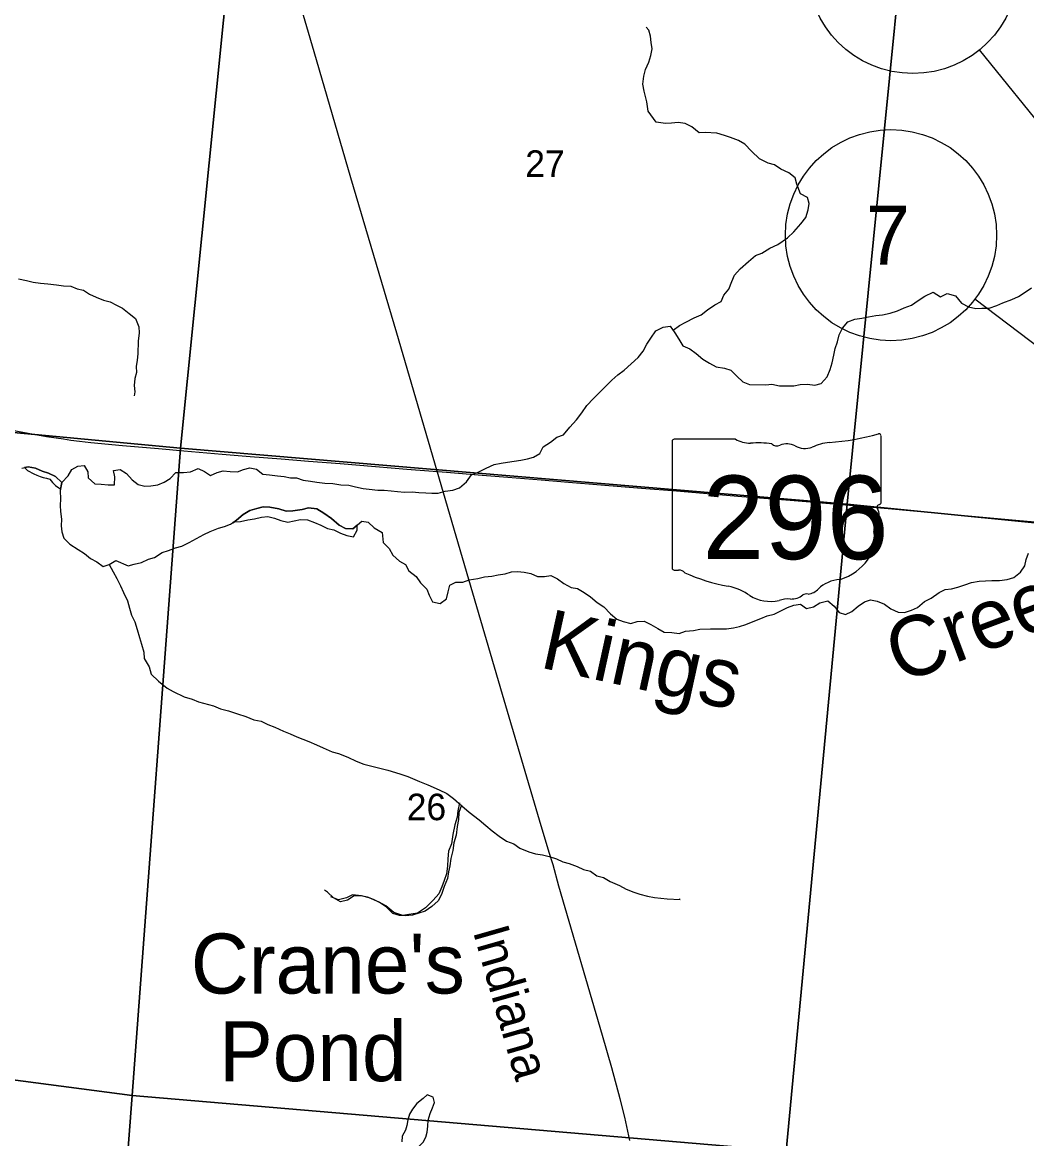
# Model space of a CAD drawing. Extents: x 0 to 1101, y 0 to 440.
# Drawn here: x 194.8 to 242.4, y 64.6 to 117.4 of the extents above; entities that cross this region are included whole.
import ezdxf

# ---------------------------------------------------------------- set-up
doc = ezdxf.new("R2010")
doc.units = 0
for name, color, linetype in [('GM_X_Minor_Lake', 7, 'Continuous'), ('GM_X_Minor_River', 7, 'Continuous'), ('GM_X_Minor_River_Text', 7, 'Continuous'), ('GM_X_Rail_Line', 7, 'Continuous'), ('GM_X_Rail_Line_Text', 7, 'Continuous'), ('GM_X_Section', 7, 'Continuous'), ('GM_X_Section_Text', 7, 'Continuous'), ('GM_X_State_Location', 7, 'Continuous'), ('GM_X_State_Route', 7, 'Continuous'), ('GM_X_State_Shield', 7, 'Continuous'), ('SH_Masking', 7, 'Continuous'), ('SH_Text', 7, 'Continuous')]:
    doc.layers.add(name, color=color, linetype=linetype)

msp = doc.modelspace()

# ---------------------------------------------------------------- linework, layer by layer
at = {"layer": 'GM_X_Minor_Lake'}
for points in [[(196.719, 95.648), (196.408, 95.92), (196.083, 96.089), (195.778, 96.178), (195.464, 96.313), (195.124, 96.38), (194.949, 96.347)], [(194.949, 96.347), (195.093, 96.204), (195.388, 96.047), (195.533, 95.99), (195.684, 95.93), (195.832, 95.882), (195.989, 95.84), (196.14, 95.792), (196.275, 95.644), (196.42, 95.502), (196.565, 95.382), (196.653, 95.312)], [(196.653, 95.312), (196.719, 95.648)], [(210.69, 93.617), (210.487, 93.446), (210.146, 93.468), (209.844, 93.625), (209.488, 93.933), (209.12, 94.184), (208.785, 94.399), (208.398, 94.434), (208.1, 94.362), (207.643, 94.296), (207.335, 94.282), (206.986, 94.395), (206.555, 94.477), (206.248, 94.486), (205.939, 94.415), (205.617, 94.311), (205.293, 94.126), (204.989, 93.85), (204.809, 93.735)], [(204.809, 93.735), (204.884, 93.773), (205.169, 93.798), (205.513, 93.868), (205.834, 93.927), (206.166, 93.997), (206.474, 94.034), (206.779, 93.956), (207.083, 93.833), (207.411, 93.755), (207.709, 93.826), (208.018, 93.885), (208.348, 93.875), (208.675, 93.751), (208.978, 93.617), (209.292, 93.459), (209.598, 93.393), (209.9, 93.235), (210.205, 93.135), (210.522, 93.068), (210.702, 93.383), (210.69, 93.617)], [(212.694, 60.754), (212.77, 60.75), (212.842, 60.999), (212.851, 61.545), (212.798, 61.807), (212.769, 62.126), (212.784, 62.365), (212.8, 62.637), (212.85, 62.932), (212.933, 63.17), (213.05, 63.453), (213.224, 63.689), (213.444, 63.947), (213.618, 64.184), (213.825, 64.397), (213.953, 64.622), (214.014, 64.86), (214.041, 65.156), (214.057, 65.428), (214.152, 65.745), (214.27, 66.017), (214.365, 66.277), (214.289, 66.528), (214.019, 66.635)], [(214.019, 66.635), (213.823, 66.467), (213.524, 66.221), (213.316, 65.963), (213.176, 65.715), (213.093, 65.443), (213.055, 65.182), (212.983, 64.955), (212.831, 64.673), (212.804, 64.401)]]:
    msp.add_lwpolyline(points, dxfattribs=at)
at = {"layer": 'GM_X_Minor_River'}
for points in [[(225.652, 102.856), (225.956, 103.071), (226.256, 103.234), (226.649, 103.439), (226.984, 103.577), (227.287, 103.82), (227.635, 104.049), (227.924, 104.212), (228.058, 104.516), (228.295, 104.806), (228.441, 105.156), (228.564, 105.46), (228.835, 105.76), (229.221, 106.103), (229.559, 106.39), (229.858, 106.506), (230.241, 106.735), (230.61, 106.918), (231.075, 107.224), (231.368, 107.512), (231.709, 107.89), (231.934, 108.192), (232.047, 108.554), (232.09, 108.849), (232.019, 109.148), (231.694, 109.318), (231.514, 109.78), (231.432, 110.079), (231.131, 110.316), (230.76, 110.487), (230.459, 110.69), (230.154, 110.768), (229.739, 110.974), (229.362, 111.328), (229.053, 111.668), (228.751, 111.848), (228.379, 111.985), (228.086, 112.085), (227.725, 112.187), (227.18, 112.226), (226.883, 112.2), (226.538, 112.484), (226.224, 112.642), (225.895, 112.697), (225.587, 112.661), (225.302, 112.647), (224.849, 112.717), (224.477, 113.23), (224.41, 113.677), (224.288, 114.172), (224.218, 114.516), (224.263, 114.892), (224.352, 115.208), (224.499, 115.558), (224.599, 115.863), (224.665, 116.18), (224.617, 116.479), (224.592, 116.776), (224.51, 117.075), (224.377, 117.216)], [(194.667, 105.289), (195.04, 105.209), (195.357, 105.131), (195.709, 105.087), (196.049, 105.054), (196.457, 104.996), (196.787, 104.963), (197.139, 104.942), (197.442, 104.807), (197.737, 104.753), (198.027, 104.561), (198.342, 104.427), (198.679, 104.28), (198.996, 104.202), (199.298, 104.033), (199.59, 103.899), (199.902, 103.65), (200.202, 103.413), (200.361, 103.02), (200.376, 102.734), (200.33, 102.335), (200.313, 101.742), (200.281, 101.435), (200.238, 101.139), (200.253, 100.853), (200.176, 100.559), (200.132, 100.24), (200.169, 99.942), (200.14, 99.738)], [(213.611, 95.17), (213.952, 95.148), (214.237, 95.14), (214.533, 95.142), (214.865, 95.224), (215.231, 95.27), (215.542, 95.386), (215.88, 95.673), (216.106, 95.998), (216.429, 96.137), (216.799, 96.32), (217.179, 96.491), (217.511, 96.55), (217.809, 96.598), (218.129, 96.646), (218.449, 96.705), (218.758, 96.764), (219.045, 96.836), (219.346, 97.021), (219.503, 97.324), (219.852, 97.554), (220.154, 97.785), (220.465, 97.901), (220.772, 98.269), (221.078, 98.614), (221.338, 98.937), (221.564, 99.285), (221.881, 99.618), (222.174, 99.906), (222.456, 100.195), (222.749, 100.483), (223.041, 100.737), (223.344, 100.956), (223.999, 101.554), (224.235, 101.866), (224.404, 102.192), (224.595, 102.484), (224.844, 102.819), (225.191, 103.003), (225.522, 103.05), (225.74, 102.724), (225.926, 102.433), (226.121, 102.107), (226.447, 101.972), (226.748, 101.757), (227.059, 101.485), (227.372, 101.293), (227.697, 101.112), (228.094, 101.055), (228.387, 100.966), (228.675, 100.684), (228.963, 100.412), (229.278, 100.289), (230.052, 100.266), (230.337, 100.292), (230.688, 100.224), (231.041, 100.225), (231.371, 100.226), (231.669, 100.275), (232.011, 100.299), (232.363, 100.254), (232.661, 100.337), (232.955, 100.648), (233.09, 100.998), (233.19, 101.314), (233.269, 101.666), (233.335, 101.984), (233.447, 102.3), (233.514, 102.641), (233.671, 102.945), (233.93, 103.245), (234.264, 103.384), (234.595, 103.419), (234.905, 103.49), (235.259, 103.548), (235.568, 103.585), (235.935, 103.665), (236.279, 103.78), (236.602, 103.908), (236.948, 104.046), (237.261, 104.254), (237.575, 104.473), (237.967, 104.655), (238.314, 104.439), (238.626, 104.601), (239.021, 104.475), (239.307, 104.136), (239.643, 103.954), (239.983, 103.887), (240.268, 103.901), (240.621, 103.902), (240.977, 104.017), (241.266, 104.157), (241.692, 104.316), (242.003, 104.455), (242.327, 104.651), (242.618, 104.859)], [(194.815, 96.321), (195.124, 96.38), (195.464, 96.313), (195.778, 96.178), (196.083, 96.089), (196.408, 95.92), (196.719, 95.648), (197.013, 95.959), (197.181, 96.251), (197.47, 96.414), (197.767, 96.439), (197.941, 96.149), (197.966, 95.862), (198.277, 95.579), (198.572, 95.559), (198.913, 95.537), (199.209, 95.529), (199.231, 95.905), (199.16, 96.204), (199.481, 96.263), (199.782, 96.06), (200.036, 95.767), (200.325, 95.552), (200.641, 95.463), (200.927, 95.489), (201.258, 95.536), (201.558, 95.664), (201.847, 95.827), (202.118, 96.116), (202.482, 96.117), (202.802, 96.153), (203.171, 96.302), (203.463, 96.168), (203.753, 95.965), (204.064, 96.115), (204.352, 96.198), (204.68, 96.154), (205.033, 96.144), (205.321, 96.249), (205.619, 96.343), (205.936, 96.277), (206.225, 96.04), (206.554, 95.996), (206.918, 95.962), (207.246, 95.918), (207.541, 95.864), (207.826, 95.867), (208.141, 95.755), (208.481, 95.699), (208.787, 95.655), (209.173, 95.61), (209.548, 95.587), (209.922, 95.53), (210.297, 95.508), (210.614, 95.441), (210.976, 95.362), (211.27, 95.319), (211.668, 95.273), (211.975, 95.275), (212.304, 95.243), (212.6, 95.222), (212.94, 95.19), (213.294, 95.202), (213.611, 95.17)], [(196.719, 95.648), (196.639, 95.239), (196.651, 94.873), (196.642, 94.554), (196.645, 94.268), (196.691, 93.901), (196.682, 93.593), (196.707, 93.296), (196.801, 93.007), (197.1, 92.713), (197.491, 92.462), (197.782, 92.282), (198.071, 92.045), (198.374, 91.876), (198.663, 91.662), (198.962, 91.755), (199.275, 91.94), (199.86, 91.695), (200.146, 91.766), (200.49, 91.847), (200.814, 92.009), (201.1, 92.08), (201.461, 92.332), (201.759, 92.426), (202.093, 92.553), (202.403, 92.624), (202.749, 92.797), (203.097, 92.992), (203.444, 93.176), (203.733, 93.327), (204.124, 93.475), (204.411, 93.558), (204.699, 93.664), (204.989, 93.85), (205.293, 94.126), (205.617, 94.311), (205.939, 94.415), (206.248, 94.486), (206.555, 94.477), (206.986, 94.395), (207.335, 94.282), (207.643, 94.296), (208.1, 94.362), (208.398, 94.434), (208.785, 94.399), (209.12, 94.184), (209.488, 93.933), (209.844, 93.625), (210.146, 93.468), (210.487, 93.446), (210.919, 93.81), (211.213, 93.756), (211.502, 93.496), (211.882, 93.268), (211.925, 92.798), (212.213, 92.516), (212.386, 92.191), (212.696, 91.907), (212.988, 91.762), (213.138, 91.449), (213.484, 91.187), (213.703, 90.895), (213.99, 90.59), (214.107, 90.3), (214.257, 89.988), (214.63, 89.908), (214.921, 90.128), (214.999, 90.457), (215.077, 90.774), (215.366, 90.925), (215.707, 90.915), (215.995, 91.032), (216.407, 91.089), (216.728, 91.171), (217.07, 91.206), (217.38, 91.265), (217.7, 91.313), (217.998, 91.407), (218.295, 91.432), (218.602, 91.4), (218.919, 91.334), (219.233, 91.187), (219.563, 91.189), (219.861, 91.237), (220.175, 91.079), (220.476, 90.854), (220.834, 90.66), (221.129, 90.617), (221.442, 90.436), (221.744, 90.222), (222.066, 89.961), (222.379, 89.746), (222.699, 89.417), (222.999, 89.168), (223.292, 89.056), (223.654, 88.965), (223.952, 89.059), (224.283, 89.072), (224.597, 88.915), (224.933, 88.722), (225.235, 88.553)], [(225.235, 88.553), (225.6, 88.542), (225.939, 88.486), (226.25, 88.591), (226.627, 88.637), (226.925, 88.697), (227.426, 88.705), (227.802, 88.705), (228.189, 88.705), (228.509, 88.752), (228.807, 88.812), (229.094, 88.918), (229.451, 89.056), (229.809, 89.205), (230.108, 89.322), (230.44, 89.403), (230.752, 89.565), (231.076, 89.727), (231.364, 89.833), (231.684, 89.88), (231.974, 89.666), (232.295, 89.748), (232.608, 89.944), (232.986, 90.035), (233.275, 89.776), (233.517, 89.483), (233.821, 89.382), (234.11, 89.522), (234.414, 89.787), (234.715, 89.984), (235.003, 90.078), (235.32, 90.023), (235.657, 89.876), (235.97, 89.661), (236.317, 89.491), (236.613, 89.482), (236.935, 89.598), (237.224, 89.726), (237.551, 90.002), (237.874, 90.164), (238.246, 90.427), (238.535, 90.567), (238.832, 90.604), (239.13, 90.675), (239.475, 90.79), (239.786, 90.907), (240.14, 90.965), (240.448, 90.978), (240.744, 90.992), (241.109, 90.993), (241.475, 91.05), (241.785, 91.144), (242.111, 91.386), (242.313, 91.688), (242.368, 91.995), (242.479, 92.289)], [(198.95, 91.752), (199.145, 91.407), (199.318, 91.094), (199.49, 90.746), (199.629, 90.434), (199.823, 90.04), (199.915, 89.683), (200.019, 89.36), (200.169, 89.035), (200.284, 88.678), (200.387, 88.298), (200.491, 87.975), (200.594, 87.606), (200.619, 87.297), (200.847, 86.914), (200.95, 86.556), (201.294, 86.226), (201.694, 85.895), (201.985, 85.738), (202.513, 85.493), (202.886, 85.38), (203.178, 85.245), (203.901, 85.064), (204.227, 84.917), (204.611, 84.826), (205.028, 84.676), (205.423, 84.562), (205.806, 84.402), (206.145, 84.335), (206.471, 84.176), (206.797, 84.052), (207.213, 83.869), (207.517, 83.734), (207.843, 83.599), (208.405, 83.365), (208.765, 83.217), (209.091, 83.07), (209.507, 82.887), (209.812, 82.798), (210.262, 82.624), (210.655, 82.441), (211.016, 82.305), (211.388, 82.202), (212.146, 82.02), (212.721, 81.843), (213.093, 81.717), (213.655, 81.472), (214.049, 81.312), (214.577, 81.079), (214.948, 80.908), (215.26, 80.67), (215.66, 80.327), (215.993, 80.032), (216.472, 79.663), (216.794, 79.391), (217.083, 79.143), (217.428, 78.892), (217.763, 78.654), (218.112, 78.529), (218.402, 78.315), (218.818, 78.143), (219.145, 78.053), (219.474, 77.997), (219.791, 77.931), (220.129, 77.818), (220.432, 77.672), (220.737, 77.594), (221.109, 77.446), (221.412, 77.311), (221.74, 77.222), (222.041, 77.007), (222.357, 76.929), (222.682, 76.737), (223.121, 76.552), (223.434, 76.383), (223.794, 76.235), (224.087, 76.135), (224.449, 76.044), (224.778, 75.989), (225.072, 75.946), (225.379, 75.914), (225.993, 75.895), (225.948, 75.908)], [(215.535, 80.466), (215.464, 80.081), (215.425, 79.786), (215.317, 79.424), (215.219, 78.959), (215.167, 78.527), (215.026, 78.177), (214.997, 77.813), (214.969, 77.461), (214.93, 77.098), (214.823, 76.781), (214.705, 76.487), (214.563, 76.148), (214.298, 75.856), (213.94, 75.486), (213.551, 75.241), (213.141, 75.179), (212.857, 75.126), (212.44, 75.269), (212.047, 75.594), (211.744, 75.769), (211.271, 75.969), (210.898, 76.066), (210.479, 76.106), (210.193, 75.963), (209.806, 75.866), (209.445, 76.019)], [(215.635, 80.349), (215.514, 80.012), (215.493, 79.681), (215.426, 79.34), (215.38, 78.93), (215.267, 78.568), (215.234, 78.204), (215.132, 77.83), (215.087, 77.488), (215.022, 77.193), (214.978, 76.875), (214.82, 76.502), (214.695, 76.129), (214.538, 75.825), (214.234, 75.549), (213.909, 75.33), (213.61, 75.236), (213.323, 75.142), (212.98, 75.118), (212.696, 75.126), (212.38, 75.227), (212.093, 75.521), (211.792, 75.736), (211.477, 75.882), (211.185, 76.005), (210.868, 76.06), (210.549, 76.058), (210.247, 75.85), (209.914, 75.78), (209.579, 75.973), (209.29, 76.233), (209.156, 76.328)]]:
    msp.add_lwpolyline(points, dxfattribs=at)
at = {"layer": 'GM_X_Rail_Line'}
msp.add_lwpolyline([(223.608, 64.467), (223.363, 65.583), (223.154, 66.443), (222.758, 67.914), (222.312, 69.443), (220.238, 76.525), (219.974, 77.531), (219.793, 78.107), (219.325, 79.646), (217.583, 85.594), (215.984, 91.046), (212.575, 102.712), (210.401, 110.076), (208.667, 116.046), (202.393, 137.425)], dxfattribs=at)
at = {"layer": 'GM_X_Section'}
for points in [[(205.379, 127.608), (202.337, 97.26), (171.52, 100.149), (174.454, 130.113)], [(205.379, 127.608), (236.891, 124.822), (233.896, 94.609), (202.337, 97.26)], [(267.417, 122.144), (264.55, 91.562), (233.896, 94.609), (236.891, 124.822)], [(171.52, 100.149), (202.337, 97.26), (200.04, 66.605), (168.832, 70.705)], [(202.337, 97.26), (233.896, 94.609), (231.008, 63.962), (200.04, 66.605)], [(233.896, 94.609), (264.55, 91.562), (261.598, 62.219), (231.008, 63.962)], [(168.832, 70.705), (200.04, 66.605), (197.781, 37.029), (166.2, 40.464)], [(231.008, 63.962), (227.72, 34.127), (197.781, 37.029), (200.04, 66.605)]]:
    msp.add_lwpolyline(points, close=True, dxfattribs=at)
at = {"layer": 'GM_X_State_Route'}
msp.add_lwpolyline([(193.863, 98.209), (195.113, 97.978), (195.995, 97.827), (196.786, 97.705), (197.142, 97.653), (197.556, 97.604), (198.08, 97.543), (199.582, 97.396), (201.29, 97.244), (202.497, 97.14), (204.298, 96.981), (205.635, 96.872), (207.104, 96.758), (208.386, 96.654), (209.891, 96.536), (211.563, 96.4), (213.049, 96.276), (214.926, 96.124), (216.616, 95.985), (217.825, 95.893), (219.403, 95.759), (220.704, 95.652), (222.227, 95.527), (224.159, 95.367), (225.813, 95.242), (228.915, 94.984), (231.201, 94.799), (233.263, 94.626), (235.845, 94.404), (238.24, 94.19), (239.447, 94.084), (242.064, 93.845), (244.794, 93.609)], dxfattribs=at)
at = {"layer": 'GM_X_State_Shield'}
for p, q in [((235.504, 94.702), (235.504, 97.843)), ((225.617, 97.59), (225.617, 91.587)), ((228.609, 97.694), (225.714, 97.694)), ((235.503, 94.703), (235.504, 94.702))]:
    msp.add_line(p, q, dxfattribs=at)
for centre, major_axis, start_param, end_param in [((231.982, 105.879), (10.486, 0), 4.814394, 5.042369), ((235.394, 97.856), (0.11, 0), 6.141152, 7.989035), ((225.73, 97.603), (0.115, 0), 1.712693, 3.28349), ((229.299, 98.391), (1.111, 0), 4.042523, 4.731795), ((229.667, 94.323), (3.989, 0), 1.404758, 1.657858), ((230.573, 97.634), (0.321, 0), 3.836095, 5.185415), ((231.044, 96.94), (0.666, 0), 0.950623, 2.079405), ((231.904, 97.892), (0.802, 0), 4.081561, 5.145723), ((233.319, 95.86), (2.11, 0), 1.699011, 2.107814), ((235.387, 94.69), (0.118, 0), 5.05454, 6.418171), ((235.479, 94.471), (0.17, 0), 1.883978, 3.671073), ((234.395, 94.074), (1.023, 0), 5.934695, 6.695948), ((235.898, 93.388), (0.744, 0), 2.387724, 3.262537), ((232.569, 92.988), (2.623, 0), 5.101752, 6.440018), ((225.731, 91.574), (0.116, 0), 3.00124, 4.508301), ((225.748, 92.188), (0.882, 0), 4.665946, 4.897461), ((225.929, 91.24), (0.318, 0), 0.519207, 1.627899), ((229.944, 96.634), (7.572, 0), 4.195997, 4.488961), ((233.675, 89.901), (1.436, 0), 1.647645, 2.488434), ((227.686, 88.89), (2.369, 0), 0.823519, 1.323587), ((231.855, 91.005), (0.847, 0), 4.937069, 5.64225), ((230.248, 91.211), (1.503, 0), 4.026481, 4.996735), ((231.117, 89.135), (1.235, 0), 1.495662, 1.94098), ((231.227, 90.761), (0.801, 0), 4.691044, 5.507374), ((231.951, 90.18), (0.226, 0), 1.147584, 2.315152)]:
    msp.add_ellipse(centre, major_axis=major_axis, ratio=0.8, start_param=start_param, end_param=end_param, dxfattribs=at)
at = {"layer": 'SH_Masking'}
for centre in [(237.013, 120.015), (235.972, 107.356)]:
    msp.add_circle(centre, 5, dxfattribs=at)
at = {"layer": 'SH_Text'}
for p, q in [((249.491, 104.603), (240.16, 116.129)), ((248.746, 97.623), (239.949, 104.326))]:
    msp.add_line(p, q, dxfattribs=at)
for centre in [(237.013, 120.015), (235.972, 107.356)]:
    msp.add_circle(centre, 5, dxfattribs=at)

# ---------------------------------------------------------------- texts
at = {"layer": 'GM_X_Minor_River_Text'}
for s, height, rotation, p in [('Creek', 2.8408, 20.6145, (236.405, 86.098)), ('Kings', 2.8409, 347.6289, (219.269, 86.894)), ("Crane's", 2.8409, 0.0153, (202.824, 71.432)), ('Pond', 2.8409, 0.015, (204.167, 67.281))]:
    msp.add_text(s, height=height, rotation=rotation, dxfattribs=at).set_placement(p)
at = {"layer": 'GM_X_Rail_Line_Text'}
msp.add_text('Indiana', height=1.6989, rotation=285.9979, dxfattribs=at).set_placement((216.167, 74.383))
at = {"layer": 'GM_X_Section_Text'}
for s, p in [('27', (218.656, 110.119)), ('26', (213.043, 79.644))]:
    msp.add_text(s, height=1.2557, rotation=0, dxfattribs=at).set_placement(p)
at = {"layer": 'GM_X_State_Location'}
for s in ['s', 'r']:
    msp.add_text(s, height=0.00568, dxfattribs=at).set_placement((230.449, 94.19))
msp.add_text('296', height=0.00568, rotation=0, dxfattribs=at).set_placement((228.443, 93.776))
at = {"layer": 'GM_X_State_Shield'}
msp.add_text('296', height=3.9551, dxfattribs=at).set_placement((227.039, 92.01))
at = {"layer": 'SH_Text'}
msp.add_text('7', height=2.8, rotation=360, dxfattribs=at).set_placement((234.79, 105.956))

doc.saveas('drawing.dxf')
